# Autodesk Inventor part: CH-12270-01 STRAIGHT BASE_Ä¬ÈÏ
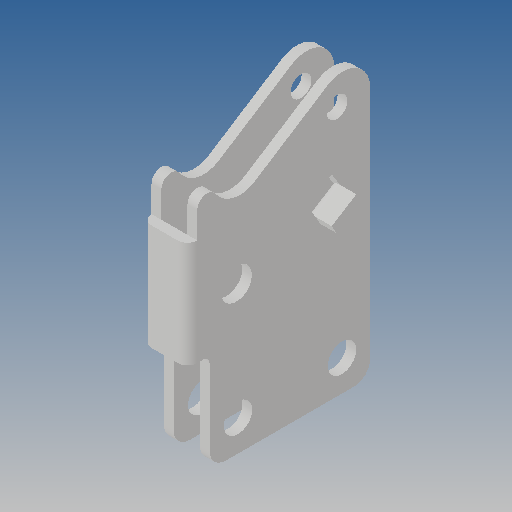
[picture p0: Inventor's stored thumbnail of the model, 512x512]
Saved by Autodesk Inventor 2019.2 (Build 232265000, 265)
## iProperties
Created: 2012-09
Part Number: CH-12270-01 STRAIGHT BASE_Ä¬ÈÏ
Material: Ogólny
Document SubType Name: Modeling
Designer: CADENGINEERING4
Density: 1 g/cm^3
Appearance: Domyślna
Author: CADENGINEERING4
Revision Number: ÈÎºÎ
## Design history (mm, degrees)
feature "NONE"
node "Bryła1"
